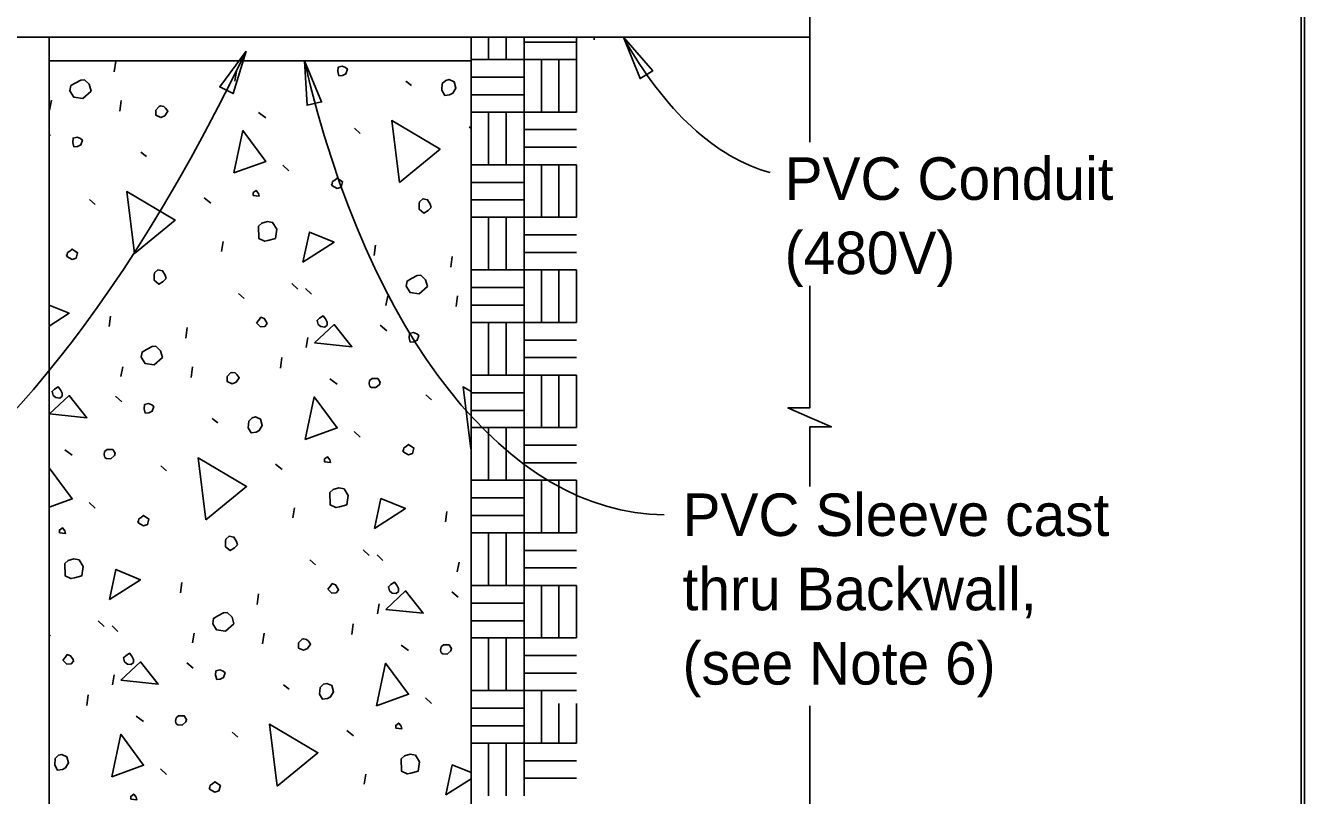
# Model space of a CAD drawing. Extents: x 0 to 30.8, y 0 to 21.2.
# Drawn here: x 26.255 to 30.8, y 4.02 to 6.756 of the extents above; entities that cross this region are included whole.
import ezdxf

# ---------------------------------------------------------------- set-up
doc = ezdxf.new("R2010")
doc.units = 0
for name, color, linetype in [('ActivePts-ConstElements', 7, 'Continuous'), ('Dimension', 7, 'Continuous'), ('Lighting', 7, 'Continuous'), ('Miscellaneous', 7, 'Continuous'), ('Miscellaneous1', 7, 'Continuous'), ('SupstrConc', 7, 'Continuous')]:
    doc.layers.add(name, color=color, linetype=linetype)

msp = doc.modelspace()

# ---------------------------------------------------------------- linework, layer by layer
at = {"layer": 'ActivePts-ConstElements'}
msp.add_lwpolyline([(0, 0), (30.7879, 0), (30.7879, 19.4596), (0, 19.4596)], close=True, dxfattribs=at)
at = {"layer": 'Dimension'}
for points in [[(29.0415, 6.3424), (29.0415, 8.629)], [(29.0415, 5.1189), (29.0415, 5.3302), (29.119, 5.3302), (29.0415, 5.364), (28.964, 5.3977), (29.0415, 5.3977), (29.0415, 5.8316)], [(29.0415, 2.169), (29.0415, 4.3387)]]:
    msp.add_lwpolyline(points, dxfattribs=at)
for points in [[(28.3793, 6.7147), (28.484, 6.5958), (28.439, 6.568)], [(27.039, 6.6658), (26.9448, 6.5385), (26.992, 6.5146)], [(27.246, 6.6314), (27.2551, 6.4733), (27.3067, 6.4851)]]:
    msp.add_lwpolyline(points, close=True, dxfattribs=at)
for centre, major_axis, ratio, start_param, end_param in [((29.1245, 8.5836), (0.1111, 2.3674), 0.464296, 2.502126, 3.038691), ((28.5479, 7.7812), (0.0241, 2.7636), 0.515084, 2.004362, 3.141607)]:
    msp.add_ellipse(centre, major_axis=major_axis, ratio=ratio, start_param=start_param, end_param=end_param, dxfattribs=at)
msp.add_open_spline([(22.5801, 4.1306), (23.0069, 4.1308), (23.8463, 4.1349), (24.524, 4.3118), (25.5501, 4.7344), (26.5058, 5.5697), (27.039, 6.6659)], degree=3, dxfattribs=at)
at = {"layer": 'Lighting'}
msp.add_line((29.0415, 6.7147), (25.9826, 6.7147), dxfattribs=at)
at = {"layer": 'Miscellaneous'}
for p, q in [((27.9005, 6.7147), (27.9005, 6.6354)), ((27.963, 6.7147), (27.963, 6.6354)), ((28.0267, 6.6354), (28.0267, 6.7147)), ((28.0267, 6.6979), (28.213, 6.6979)), ((28.213, 6.7147), (28.213, 6.6354)), ((28.2755, 6.7147), (28.2755, 6.7058)), ((27.838, 6.6314), (26.338, 6.6314)), ((26.57, 6.5922), (26.5755, 6.6299)), ((26.9981, 6.5594), (27.0042, 6.5947)), ((27.838, 6.6354), (28.0267, 6.6354)), ((28.0267, 6.2616), (28.0267, 6.6354)), ((28.0267, 6.6354), (28.213, 6.6354)), ((28.088, 6.4491), (28.088, 6.6354)), ((28.1505, 6.4491), (28.1505, 6.6354)), ((28.213, 6.4491), (28.213, 6.6354)), ((27.6064, 6.5593), (27.626, 6.5439)), ((27.838, 6.5729), (28.0267, 6.5729)), ((27.838, 6.5104), (28.0267, 6.5104)), ((26.3401, 6.4555), (26.3462, 6.4908)), ((26.5894, 6.4524), (26.5948, 6.4901)), ((27.0825, 6.4474), (27.1083, 6.4284)), ((27.838, 6.4491), (28.213, 6.4491)), ((27.838, 6.4491), (27.838, 6.2616)), ((27.9005, 6.4491), (27.9005, 6.2616)), ((27.963, 6.4491), (27.963, 6.2616)), ((26.3379, 6.3704), (26.3434, 6.3658)), ((27.4236, 6.3913), (27.4439, 6.3734)), ((27.8311, 6.3969), (27.8379, 6.3911)), ((28.0267, 6.3866), (28.213, 6.3866)), ((28.0267, 6.3241), (28.213, 6.3241)), ((26.6646, 6.307), (26.6843, 6.2915)), ((27.1687, 6.2609), (27.1897, 6.2406)), ((27.838, 6.2616), (28.0267, 6.2616)), ((28.0267, 6.2616), (28.213, 6.2616)), ((28.0267, 5.8879), (28.0267, 6.2616)), ((28.088, 6.0754), (28.088, 6.2616)), ((28.1505, 6.0754), (28.1505, 6.2616)), ((28.213, 6.0754), (28.213, 6.2616)), ((27.838, 6.1991), (28.0267, 6.1991)), ((26.4819, 6.1389), (26.5022, 6.1211)), ((26.8893, 6.1446), (26.9126, 6.125)), ((27.838, 6.1366), (28.0267, 6.1366)), ((27.838, 6.0754), (28.213, 6.0754)), ((27.838, 6.0754), (27.838, 5.8879)), ((27.9005, 6.0754), (27.9005, 5.8879)), ((27.963, 6.0754), (27.963, 5.8879)), ((28.0267, 6.0129), (28.213, 6.0129)), ((26.9507, 5.954), (26.9568, 5.9893)), ((27.4931, 5.9388), (27.4985, 5.9765)), ((27.7655, 5.8979), (27.7709, 5.9356)), ((28.0267, 5.9504), (28.213, 5.9504)), ((27.838, 5.8878), (28.0267, 5.8878)), ((28.0267, 5.8879), (28.213, 5.8879)), ((28.0267, 5.514), (28.0267, 5.8878)), ((28.088, 5.7015), (28.088, 5.8878)), ((28.1505, 5.7015), (28.1505, 5.8878)), ((28.213, 5.7015), (28.213, 5.8878)), ((27.2013, 5.8399), (27.2222, 5.8197)), ((27.2501, 5.822), (27.271, 5.8017)), ((27.838, 5.8253), (28.0267, 5.8253)), ((27.0114, 5.8046), (27.0317, 5.7868)), ((27.5355, 5.7613), (27.5416, 5.7965)), ((27.7848, 5.7582), (27.7902, 5.7959)), ((27.838, 5.7628), (28.0267, 5.7628)), ((26.5513, 5.6865), (26.5567, 5.7242)), ((26.8237, 5.6456), (26.8291, 5.6833)), ((27.5155, 5.6912), (27.5388, 5.6716)), ((27.838, 5.7015), (28.213, 5.7015)), ((27.838, 5.7015), (27.838, 5.514)), ((27.9005, 5.7015), (27.9005, 5.514)), ((27.963, 5.7015), (27.963, 5.514)), ((27.2518, 5.6128), (27.2578, 5.648)), ((28.0267, 5.639), (28.213, 5.639)), ((27.1602, 5.5391), (27.1657, 5.5768)), ((28.0267, 5.5765), (28.213, 5.5765)), ((26.5937, 5.5089), (26.5998, 5.5442)), ((26.843, 5.5058), (26.8484, 5.5435)), ((27.3361, 5.5008), (27.3619, 5.4818)), ((27.838, 5.514), (28.0267, 5.514)), ((28.0267, 5.1403), (28.0267, 5.514)), ((28.0267, 5.514), (28.213, 5.514)), ((28.088, 5.3278), (28.088, 5.514)), ((28.1505, 5.3278), (28.1505, 5.514)), ((28.213, 5.3278), (28.213, 5.514)), ((26.5737, 5.4388), (26.5971, 5.4192)), ((27.6773, 5.4447), (27.6976, 5.4268)), ((27.838, 5.4515), (28.0267, 5.4515)), ((27.838, 5.389), (28.0267, 5.389)), ((26.9182, 5.3603), (26.9379, 5.3449)), ((27.838, 5.3278), (28.213, 5.3278)), ((27.838, 5.3278), (27.838, 5.1403)), ((27.9005, 5.3278), (27.9005, 5.1403)), ((27.963, 5.3278), (27.963, 5.1403)), ((27.4223, 5.3143), (27.4433, 5.294)), ((26.3943, 5.2484), (26.4201, 5.2295)), ((28.0267, 5.2653), (28.213, 5.2653)), ((26.7355, 5.1923), (26.7558, 5.1745)), ((27.1429, 5.198), (27.1663, 5.1783)), ((28.0267, 5.2028), (28.213, 5.2028)), ((27.838, 5.1403), (28.0267, 5.1403)), ((28.0267, 4.7665), (28.0267, 5.1403)), ((28.0267, 5.1403), (28.213, 5.1403)), ((28.088, 4.954), (28.088, 5.1403)), ((28.1505, 4.954), (28.1505, 5.1403)), ((28.213, 4.954), (28.213, 5.1403)), ((26.4806, 5.0619), (26.5015, 5.0416)), ((27.838, 5.0778), (28.0267, 5.0778)), ((27.2043, 5.0074), (27.2104, 5.0426)), ((27.7467, 4.9922), (27.7522, 5.0299)), ((27.838, 5.0153), (28.0267, 5.0153)), ((27.838, 4.954), (28.213, 4.954)), ((27.838, 4.954), (27.838, 4.7665)), ((27.9005, 4.954), (27.9005, 4.7665)), ((27.963, 4.954), (27.963, 4.7665)), ((27.4549, 4.8933), (27.4759, 4.8731)), ((27.5037, 4.8754), (27.5247, 4.8551)), ((28.0267, 4.8915), (28.213, 4.8915)), ((27.2651, 4.858), (27.2854, 4.8401)), ((27.7891, 4.8147), (27.7952, 4.8499)), ((28.0267, 4.829), (28.213, 4.829)), ((26.805, 4.7399), (26.8104, 4.7776)), ((27.0773, 4.699), (27.0828, 4.7367)), ((27.7691, 4.7446), (27.7925, 4.725)), ((27.838, 4.7665), (28.0267, 4.7665)), ((28.0267, 4.7665), (28.213, 4.7665)), ((28.0267, 4.3928), (28.0267, 4.7665)), ((28.088, 4.5803), (28.088, 4.7665)), ((28.1505, 4.5803), (28.1505, 4.7665)), ((28.213, 4.5803), (28.213, 4.7665)), ((27.5054, 4.6662), (27.5115, 4.7014)), ((27.838, 4.704), (28.0267, 4.704)), ((26.5131, 4.641), (26.5341, 4.6207)), ((27.838, 4.6415), (28.0267, 4.6415)), ((26.3379, 4.5928), (26.3436, 4.5878)), ((26.5619, 4.623), (26.5829, 4.6027)), ((26.8474, 4.5623), (26.8534, 4.5976)), ((27.0967, 4.5592), (27.1021, 4.5969)), ((27.4139, 4.5925), (27.4193, 4.6302)), ((27.5898, 4.5542), (27.6156, 4.5352)), ((27.838, 4.5803), (28.213, 4.5803)), ((27.9005, 4.5803), (27.9005, 4.3928)), ((27.963, 4.5803), (27.963, 4.3928)), ((28.0267, 4.5178), (28.213, 4.5178)), ((26.8273, 4.4922), (26.8507, 4.4726)), ((28.0267, 4.4553), (28.213, 4.4553)), ((26.5636, 4.4138), (26.5697, 4.4491)), ((27.1719, 4.4137), (27.1915, 4.3983)), ((26.4721, 4.3401), (26.4775, 4.3778)), ((27.676, 4.3676), (27.6969, 4.3474)), ((27.838, 4.3928), (28.0267, 4.3928)), ((28.0267, 4.3928), (28.213, 4.3928)), ((28.0267, 4.019), (28.0267, 4.3928)), ((28.088, 4.2065), (28.088, 4.3928)), ((27.838, 4.3303), (28.0267, 4.3303)), ((28.1505, 4.2066), (28.1505, 4.3469)), ((28.213, 4.2066), (28.213, 4.3469)), ((26.648, 4.3018), (26.6738, 4.2829)), ((26.9891, 4.2457), (27.0094, 4.2279)), ((27.3966, 4.2514), (27.4199, 4.2317)), ((27.838, 4.2678), (28.0267, 4.2678)), ((27.838, 4.2065), (28.213, 4.2065)), ((27.9005, 4.2065), (27.9005, 4.019)), ((27.963, 4.2065), (27.963, 4.019)), ((28.0267, 4.144), (28.213, 4.144)), ((26.7342, 4.1153), (26.7552, 4.095)), ((27.458, 4.0608), (27.4641, 4.096)), ((28.0267, 4.0815), (28.213, 4.0815))]:
    msp.add_line(p, q, dxfattribs=at)
for points in [[(27.3644, 6.5928), (27.3683, 6.5783), (27.3811, 6.5792), (27.3925, 6.5848), (27.3983, 6.6019), (27.3915, 6.6078), (27.3799, 6.6125), (27.3654, 6.6086), (27.3644, 6.5928)], [(26.4123, 6.5241), (26.426, 6.5019), (26.4582, 6.4975), (26.4875, 6.5235), (26.481, 6.5477), (26.4638, 6.5637), (26.4511, 6.5629), (26.4306, 6.5523), (26.415, 6.5429), (26.4123, 6.5241)], [(27.7357, 6.55), (27.7343, 6.5263), (27.7443, 6.5083), (27.7618, 6.5104), (27.7733, 6.516), (27.7839, 6.5344), (27.778, 6.5561), (27.7603, 6.5643), (27.7482, 6.5611), (27.7357, 6.55)], [(26.7179, 6.4558), (26.7176, 6.4376), (26.7353, 6.4294), (26.7491, 6.4357), (26.7604, 6.4517), (26.7523, 6.4625), (26.7456, 6.4684), (26.7346, 6.4707), (26.7298, 6.4694), (26.7179, 6.4558)], [(27.5839, 6.1987), (27.556, 6.419), (27.7281, 6.3176), (27.5839, 6.1987)], [(26.9951, 6.2325), (27.0272, 6.3834), (27.1085, 6.2732), (26.9951, 6.2325)], [(26.4227, 6.3405), (26.4266, 6.326), (26.4393, 6.3268), (26.4507, 6.3325), (26.4565, 6.3495), (26.4497, 6.3555), (26.4381, 6.3602), (26.4236, 6.3563), (26.4227, 6.3405)], [(27.3434, 6.1886), (27.3617, 6.178), (27.3762, 6.1819), (27.3813, 6.2014), (27.3623, 6.2144), (27.354, 6.207), (27.3449, 6.202), (27.3434, 6.1886), (27.3421, 6.1934)], [(26.6422, 5.9464), (26.6142, 6.1666), (26.7863, 6.0652), (26.6422, 5.9464)], [(27.0632, 6.1524), (27.0844, 6.1503), (27.0819, 6.1599), (27.0738, 6.1707), (27.063, 6.1627), (27.0632, 6.1524)], [(27.6538, 6.1217), (27.6535, 6.1035), (27.6701, 6.0898), (27.6857, 6.0991), (27.6958, 6.1096), (27.6926, 6.1217), (27.6832, 6.1373), (27.6668, 6.1407), (27.6542, 6.1295), (27.6538, 6.1217)], [(27.082, 6.0435), (27.0833, 5.9999), (27.1041, 5.9899), (27.1162, 5.9931), (27.1428, 6.0003), (27.1471, 6.0325), (27.1327, 6.0571), (27.1139, 6.0598), (27.0945, 6.0546), (27.082, 6.0435)], [(27.2406, 5.9152), (27.2637, 6.0223), (27.351, 5.9862), (27.2406, 5.9152)], [(26.4016, 5.9363), (26.4199, 5.9256), (26.4344, 5.9295), (26.4396, 5.949), (26.4205, 5.962), (26.4122, 5.9546), (26.4032, 5.9496), (26.4016, 5.9363), (26.4003, 5.9411)], [(26.712, 5.8693), (26.7117, 5.8511), (26.7283, 5.8374), (26.7439, 5.8468), (26.754, 5.8573), (26.7508, 5.8694), (26.7414, 5.885), (26.725, 5.8883), (26.7125, 5.8772), (26.712, 5.8693)], [(27.6077, 5.8298), (27.6214, 5.8076), (27.6537, 5.8033), (27.6829, 5.8292), (27.6765, 5.8534), (27.6592, 5.8695), (27.6465, 5.8687), (27.6261, 5.858), (27.6104, 5.8486), (27.6077, 5.8298)], [(26.3379, 5.7633), (26.4092, 5.7338), (26.3379, 5.688)], [(27.0756, 5.7002), (27.0898, 5.6859), (27.105, 5.6873), (27.1127, 5.6972), (27.1114, 5.702), (27.1027, 5.7152), (27.0911, 5.7198), (27.0834, 5.71), (27.0756, 5.7002)], [(27.2812, 5.6284), (27.3517, 5.6939), (27.4143, 5.6149), (27.2812, 5.6284)], [(27.2947, 5.6942), (27.3045, 5.6864), (27.3179, 5.6848), (27.3262, 5.6923), (27.3261, 5.7026), (27.3204, 5.714), (27.3123, 5.7248), (27.2991, 5.7161), (27.2908, 5.7086), (27.2947, 5.6942)], [(27.6181, 5.6462), (27.622, 5.6317), (27.6347, 5.6326), (27.6461, 5.6382), (27.6519, 5.6553), (27.6451, 5.6612), (27.6335, 5.6659), (27.619, 5.662), (27.6181, 5.6462)], [(26.6659, 5.5775), (26.6797, 5.5552), (26.7119, 5.5509), (26.7412, 5.5769), (26.7347, 5.601), (26.7174, 5.6171), (26.7047, 5.6163), (26.6843, 5.6057), (26.6687, 5.5963), (26.6659, 5.5775)], [(26.9715, 5.5092), (26.9712, 5.491), (26.9889, 5.4828), (27.0028, 5.4891), (27.014, 5.5051), (27.006, 5.5159), (26.9992, 5.5218), (26.9883, 5.524), (26.9834, 5.5228), (26.9715, 5.5092)], [(27.4779, 5.4741), (27.484, 5.4705), (27.4998, 5.4696), (27.5123, 5.4807), (27.5152, 5.4893), (27.5065, 5.5024), (27.4859, 5.5021), (27.4775, 5.4947), (27.4753, 5.4837), (27.4779, 5.4741)], [(26.3529, 5.4418), (26.3627, 5.4341), (26.3761, 5.4325), (26.3845, 5.4399), (26.3843, 5.4502), (26.3786, 5.4616), (26.3706, 5.4724), (26.3574, 5.4637), (26.349, 5.4563), (26.3529, 5.4418)], [(27.8376, 5.2521), (27.8096, 5.4724), (27.8379, 5.4557)], [(26.3394, 5.3761), (26.4099, 5.4415), (26.4725, 5.3626), (26.3394, 5.3761)], [(26.6763, 5.3939), (26.6802, 5.3794), (26.6929, 5.3802), (26.7043, 5.3859), (26.7101, 5.4029), (26.7033, 5.4089), (26.6917, 5.4135), (26.6773, 5.4097), (26.6763, 5.3939)], [(27.2488, 5.2859), (27.2808, 5.4368), (27.3621, 5.3266), (27.2488, 5.2859)], [(27.0476, 5.351), (27.0461, 5.3273), (27.0561, 5.3093), (27.0737, 5.3114), (27.0851, 5.3171), (27.0957, 5.3354), (27.0899, 5.3572), (27.0722, 5.3654), (27.0601, 5.3621), (27.0476, 5.351)], [(26.5361, 5.2217), (26.5422, 5.2182), (26.558, 5.2172), (26.5705, 5.2284), (26.5734, 5.2369), (26.5647, 5.2501), (26.5441, 5.2498), (26.5357, 5.2423), (26.5335, 5.2314), (26.5361, 5.2217)], [(27.597, 5.242), (27.6154, 5.2314), (27.6299, 5.2353), (27.635, 5.2548), (27.616, 5.2678), (27.6076, 5.2604), (27.5986, 5.2554), (27.597, 5.242), (27.5957, 5.2468)], [(27.8379, 5.2524), (27.8376, 5.2521)], [(26.3379, 5.1793), (26.339, 5.1844), (26.4203, 5.0742), (26.3379, 5.0446)], [(26.8958, 4.9998), (26.8678, 5.22), (27.0399, 5.1186), (26.8958, 4.9998)], [(27.3168, 5.2057), (27.3381, 5.2037), (27.3355, 5.2133), (27.3274, 5.2241), (27.3167, 5.2161), (27.3168, 5.2057)], [(27.3356, 5.0969), (27.337, 5.0533), (27.3578, 5.0433), (27.3698, 5.0465), (27.3964, 5.0537), (27.4007, 5.0859), (27.3864, 5.1105), (27.3675, 5.1132), (27.3482, 5.108), (27.3356, 5.0969)], [(27.4943, 4.9686), (27.5173, 5.0757), (27.6046, 5.0396), (27.4943, 4.9686)], [(26.6552, 4.9896), (26.6736, 4.979), (26.6881, 4.9829), (26.6932, 5.0024), (26.6742, 5.0154), (26.6658, 5.008), (26.6568, 5.003), (26.6552, 4.9896), (26.6539, 4.9945)], [(26.3751, 4.9534), (26.3963, 4.9513), (26.3937, 4.961), (26.3857, 4.9718), (26.3749, 4.9637), (26.3751, 4.9534)], [(26.9656, 4.9227), (26.9653, 4.9045), (26.9819, 4.8908), (26.9975, 4.9002), (27.0077, 4.9107), (27.0044, 4.9227), (26.9951, 4.9384), (26.9786, 4.9417), (26.9661, 4.9306), (26.9656, 4.9227)], [(26.3939, 4.8446), (26.3952, 4.8009), (26.416, 4.791), (26.4281, 4.7942), (26.4546, 4.8013), (26.4589, 4.8335), (26.4446, 4.8581), (26.4257, 4.8609), (26.4064, 4.8557), (26.3939, 4.8446)], [(26.5525, 4.7162), (26.5755, 4.8234), (26.6629, 4.7872), (26.5525, 4.7162)], [(27.3293, 4.7536), (27.3435, 4.7392), (27.3586, 4.7407), (27.3663, 4.7505), (27.365, 4.7554), (27.3563, 4.7686), (27.3447, 4.7732), (27.337, 4.7634), (27.3293, 4.7536)], [(27.5483, 4.7475), (27.5581, 4.7398), (27.5715, 4.7382), (27.5799, 4.7456), (27.5797, 4.756), (27.5741, 4.7674), (27.566, 4.7782), (27.5528, 4.7695), (27.5444, 4.762), (27.5483, 4.7475)], [(27.5349, 4.6818), (27.6053, 4.7473), (27.6679, 4.6683), (27.5349, 4.6818)], [(26.9196, 4.6308), (26.9333, 4.6086), (26.9655, 4.6043), (26.9948, 4.6303), (26.9883, 4.6544), (26.9711, 4.6705), (26.9584, 4.6697), (26.9379, 4.659), (26.9223, 4.6497), (26.9196, 4.6308)], [(27.2252, 4.5626), (27.2249, 4.5444), (27.2426, 4.5362), (27.2564, 4.5425), (27.2677, 4.5585), (27.2596, 4.5692), (27.2528, 4.5752), (27.2419, 4.5774), (27.2371, 4.5761), (27.2252, 4.5626)], [(27.7315, 4.5275), (27.7376, 4.5239), (27.7534, 4.523), (27.766, 4.5341), (27.7689, 4.5426), (27.7601, 4.5558), (27.7395, 4.5555), (27.7312, 4.5481), (27.7289, 4.5371), (27.7315, 4.5275)], [(26.3875, 4.5012), (26.4017, 4.4869), (26.4168, 4.4884), (26.4246, 4.4982), (26.4233, 4.503), (26.4145, 4.5162), (26.4029, 4.5209), (26.3952, 4.511), (26.3875, 4.5012)], [(26.6065, 4.4952), (26.6164, 4.4875), (26.6297, 4.4859), (26.6381, 4.4933), (26.6379, 4.5036), (26.6323, 4.515), (26.6242, 4.5258), (26.611, 4.5171), (26.6026, 4.5097), (26.6065, 4.4952)], [(26.5931, 4.4295), (26.6635, 4.4949), (26.7261, 4.4159), (26.5931, 4.4295)], [(26.93, 4.4473), (26.9338, 4.4328), (26.9466, 4.4336), (26.958, 4.4393), (26.9638, 4.4563), (26.957, 4.4623), (26.9454, 4.4669), (26.9309, 4.4631), (26.93, 4.4473)], [(27.5024, 4.3393), (27.5344, 4.4902), (27.6157, 4.38), (27.5024, 4.3393)], [(27.3012, 4.4044), (27.2998, 4.3807), (27.3098, 4.3627), (27.3273, 4.3648), (27.3388, 4.3705), (27.3494, 4.3888), (27.3435, 4.4106), (27.3258, 4.4188), (27.3138, 4.4155), (27.3012, 4.4044)], [(26.7897, 4.2751), (26.7959, 4.2716), (26.8116, 4.2706), (26.8242, 4.2818), (26.8271, 4.2903), (26.8184, 4.3035), (26.7978, 4.3031), (26.7894, 4.2957), (26.7871, 4.2848), (26.7897, 4.2751)], [(27.1494, 4.0531), (27.1215, 4.2734), (27.2936, 4.172), (27.1494, 4.0531)], [(27.5705, 4.2591), (27.5917, 4.2571), (27.5891, 4.2667), (27.5811, 4.2775), (27.5703, 4.2694), (27.5705, 4.2591)], [(26.5606, 4.0869), (26.5927, 4.2378), (26.674, 4.1276), (26.5606, 4.0869)], [(26.3594, 4.152), (26.358, 4.1284), (26.368, 4.1103), (26.3856, 4.1125), (26.397, 4.1181), (26.4076, 4.1365), (26.4018, 4.1582), (26.384, 4.1664), (26.372, 4.1632), (26.3594, 4.152)], [(27.5893, 4.1503), (27.5906, 4.1067), (27.6114, 4.0967), (27.6235, 4.0999), (27.65, 4.1071), (27.6544, 4.1393), (27.64, 4.1639), (27.6211, 4.1666), (27.6018, 4.1614), (27.5893, 4.1503)], [(27.7479, 4.022), (27.771, 4.1291), (27.8379, 4.1014)], [(26.9089, 4.043), (26.9272, 4.0324), (26.9417, 4.0363), (26.9469, 4.0558), (26.9278, 4.0688), (26.9195, 4.0614), (26.9105, 4.0564), (26.9089, 4.043), (26.9076, 4.0479)], [(27.8379, 4.0799), (27.7479, 4.022)], [(26.6287, 4.0068), (26.65, 4.0047), (26.6474, 4.0144), (26.6393, 4.0252), (26.6285, 4.0171), (26.6287, 4.0068)]]:
    msp.add_lwpolyline(points, dxfattribs=at)
at = {"layer": 'Miscellaneous1'}
msp.add_lwpolyline([(0, 19.8), (30.8, 19.8), (30.8, 0), (0, 0)], close=True, dxfattribs=at)
at = {"layer": 'SupstrConc'}
for p, q in [((26.338, 6.7147), (26.338, 2.2466)), ((27.838, 2.2465), (27.838, 6.7147))]:
    msp.add_line(p, q, dxfattribs=at)

# ---------------------------------------------------------------- texts
at = {"layer": 'Dimension'}
for s, p in [('PVC Conduit', (28.9525, 6.137)), ('(480V)', (28.9525, 5.873)), ('PVC Sleeve cast', (28.5897, 4.9424)), ('thru Backwall,', (28.5897, 4.6784)), ('(see Note 6)', (28.5897, 4.4144))]:
    msp.add_text(s, height=0.1512, dxfattribs=at).set_placement(p)

doc.saveas('drawing.dxf')
